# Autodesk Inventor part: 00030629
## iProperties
Created: 2011-05
Part Number: 00030629
Document SubType Name: Modeling
Designer: Administrator
Density: 1.06 g/cm^3
Material: ABS Plastic
Mass: 0.663348 g
Surface Area: 11.7563 cm^2
Volume: 0.6258 cm^3
Author: Administrator
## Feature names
1. Base1
